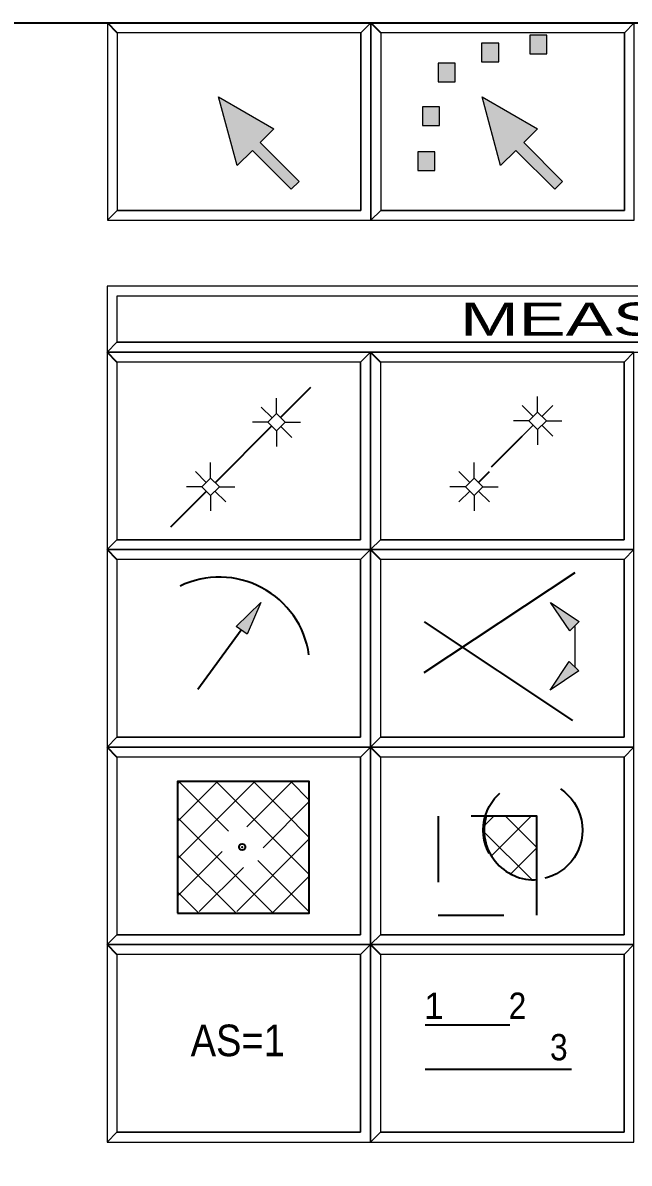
# Model space of a CAD drawing. Extents: x 95906.9 to 95918.9, y 90964.8 to 90972.9.
# Drawn here: x 95910.704 to 95911.625, y 90971.13 to 90972.862 of the extents above; entities that cross this region are included whole.
import ezdxf
from ezdxf.enums import TextEntityAlignment as Align

# ---------------------------------------------------------------- set-up
doc = ezdxf.new("R2010")
doc.units = 0
doc.header["$LTSCALE"] = 0.019
doc.header["$PDMODE"] = 32
doc.header["$PDSIZE"] = 0.0095
doc.linetypes.add('DOTTED', pattern=[1.5, 0.3, -1.2])
doc.linetypes.add('MEDIUM_DASHED', pattern=[4.5, 3, -1.5])
for name, color, linetype, lineweight in [('1', 7, 'Continuous', 25), ('11', 7, 'Continuous', 25), ('12', 7, 'Continuous', 25), ('2', 7, 'Continuous', 13), ('21', 7, 'Continuous', 25), ('3', 7, 'Continuous', 25), ('4', 7, 'Continuous', 35), ('6', 7, 'Continuous', 35), ('7', 7, 'Continuous', 35)]:
    doc.layers.add(name, color=color, linetype=linetype, lineweight=lineweight)

msp = doc.modelspace()

# ---------------------------------------------------------------- hatches: boundary and pattern name
at = {"layer": '6'}
for points in [[(95911.4737, 90972.8144), (95911.4997, 90972.8144), (95911.4997, 90972.8427), (95911.4737, 90972.8427)], [(95911.4005, 90972.8026), (95911.4265, 90972.8026), (95911.4265, 90972.8309), (95911.4005, 90972.8309)], [(95911.3344, 90972.7719), (95911.3604, 90972.7719), (95911.3604, 90972.8002), (95911.3344, 90972.8002)], [(95911.0012, 90972.7492), (95911.0851, 90972.7007), (95911.0644, 90972.68), (95911.1235, 90972.6209), (95911.1115, 90972.6089), (95911.0524, 90972.668), (95911.0292, 90972.6448)], [(95911.4012, 90972.7492), (95911.4851, 90972.7007), (95911.4644, 90972.68), (95911.5235, 90972.6209), (95911.5115, 90972.6089), (95911.4524, 90972.668), (95911.4292, 90972.6448)], [(95911.3107, 90972.7058), (95911.3367, 90972.7058), (95911.3367, 90972.7341), (95911.3107, 90972.7341)], [(95911.3036, 90972.6373), (95911.3296, 90972.6373), (95911.3296, 90972.6656), (95911.3036, 90972.6656)], [(95911.0277, 90971.945), (95911.0655, 90971.981), (95911.0443, 90971.9333)], [(95911.5346, 90971.938), (95911.505, 90971.981), (95911.5488, 90971.9526)], [(95911.5479, 90971.8772), (95911.5045, 90971.8482), (95911.5335, 90971.8916)]]:
    msp.add_hatch(color=256, dxfattribs=at).paths.add_polyline_path(points)

# ---------------------------------------------------------------- linework, layer by layer
at = {"layer": '1'}
for points in [[(95910.8323, 90972.5617), (95911.2323, 90972.5617), (95911.2323, 90972.8617), (95910.8323, 90972.8617)], [(95911.2323, 90972.5617), (95911.6323, 90972.5617), (95911.6323, 90972.8617), (95911.2323, 90972.8617)], [(95910.8318, 90972.3615), (95912.4318, 90972.3615), (95912.4318, 90972.4615), (95910.8318, 90972.4615)], [(95910.8318, 90972.0615), (95911.2318, 90972.0615), (95911.2318, 90972.3615), (95910.8318, 90972.3615)], [(95911.2318, 90972.0615), (95911.6318, 90972.0615), (95911.6318, 90972.3615), (95911.2318, 90972.3615)], [(95910.8318, 90971.7615), (95911.2318, 90971.7615), (95911.2318, 90972.0615), (95910.8318, 90972.0615)], [(95911.2318, 90971.7615), (95911.6318, 90971.7615), (95911.6318, 90972.0615), (95911.2318, 90972.0615)], [(95910.8318, 90971.4615), (95911.2318, 90971.4615), (95911.2318, 90971.7615), (95910.8318, 90971.7615)], [(95911.2318, 90971.4615), (95911.6318, 90971.4615), (95911.6318, 90971.7615), (95911.2318, 90971.7615)], [(95910.8318, 90971.1615), (95911.2318, 90971.1615), (95911.2318, 90971.4615), (95910.8318, 90971.4615)], [(95911.2318, 90971.1615), (95911.6318, 90971.1615), (95911.6318, 90971.4615), (95911.2318, 90971.4615)]]:
    msp.add_lwpolyline(points, close=True, dxfattribs=at)
at = {"layer": '11'}
for points in [[(95910.8473, 90972.5767), (95911.2173, 90972.5767), (95911.2173, 90972.8467), (95910.8473, 90972.8467)], [(95911.2473, 90972.5767), (95911.6173, 90972.5767), (95911.6173, 90972.8467), (95911.2473, 90972.8467)], [(95910.8468, 90972.0765), (95911.2168, 90972.0765), (95911.2168, 90972.3465), (95910.8468, 90972.3465)], [(95911.2468, 90972.0765), (95911.6168, 90972.0765), (95911.6168, 90972.3465), (95911.2468, 90972.3465)], [(95910.8468, 90971.7765), (95911.2168, 90971.7765), (95911.2168, 90972.0465), (95910.8468, 90972.0465)], [(95911.2468, 90971.7765), (95911.6168, 90971.7765), (95911.6168, 90972.0465), (95911.2468, 90972.0465)], [(95910.8468, 90971.4765), (95911.2168, 90971.4765), (95911.2168, 90971.7465), (95910.8468, 90971.7465)], [(95911.2468, 90971.4765), (95911.6168, 90971.4765), (95911.6168, 90971.7465), (95911.2468, 90971.7465)], [(95910.8468, 90971.1765), (95911.2168, 90971.1765), (95911.2168, 90971.4465), (95910.8468, 90971.4465)], [(95911.2468, 90971.1765), (95911.6168, 90971.1765), (95911.6168, 90971.4465), (95911.2468, 90971.4465)]]:
    msp.add_lwpolyline(points, close=True, dxfattribs=at)
at = {"layer": '12'}
msp.add_lwpolyline([(95910.8468, 90972.0765), (95911.2168, 90972.0765), (95911.2168, 90972.3465), (95910.8468, 90972.3465)], close=True, dxfattribs=at)
at = {"layer": '2'}
for points in [[(95910.8323, 90972.8617), (95910.8323, 90972.5617), (95910.8473, 90972.5767), (95910.8473, 90972.8467), (95911.2173, 90972.8467), (95911.2323, 90972.8617)], [(95911.2323, 90972.8617), (95911.2323, 90972.5617), (95911.2473, 90972.5767), (95911.2473, 90972.8467), (95911.6173, 90972.8467), (95911.6323, 90972.8617)], [(95910.8318, 90972.4615), (95910.8318, 90972.3615), (95910.8468, 90972.3765), (95910.8468, 90972.4465), (95912.4168, 90972.4465), (95912.4318, 90972.4615)], [(95910.8318, 90972.3615), (95910.8318, 90972.0615), (95910.8468, 90972.0765), (95910.8468, 90972.3465), (95911.2168, 90972.3465), (95911.2318, 90972.3615)], [(95911.2318, 90972.3615), (95911.2318, 90972.0615), (95911.2468, 90972.0765), (95911.2468, 90972.3465), (95911.6168, 90972.3465), (95911.6318, 90972.3615)], [(95910.8318, 90972.0615), (95910.8318, 90971.7615), (95910.8468, 90971.7765), (95910.8468, 90972.0465), (95911.2168, 90972.0465), (95911.2318, 90972.0615)], [(95911.2318, 90972.0615), (95911.2318, 90971.7615), (95911.2468, 90971.7765), (95911.2468, 90972.0465), (95911.6168, 90972.0465), (95911.6318, 90972.0615)], [(95910.8318, 90971.7615), (95910.8318, 90971.4615), (95910.8468, 90971.4765), (95910.8468, 90971.7465), (95911.2168, 90971.7465), (95911.2318, 90971.7615)], [(95911.2318, 90971.7615), (95911.2318, 90971.4615), (95911.2468, 90971.4765), (95911.2468, 90971.7465), (95911.6168, 90971.7465), (95911.6318, 90971.7615)], [(95910.8318, 90971.4615), (95910.8318, 90971.1615), (95910.8468, 90971.1765), (95910.8468, 90971.4465), (95911.2168, 90971.4465), (95911.2318, 90971.4615)], [(95911.2318, 90971.4615), (95911.2318, 90971.1615), (95911.2468, 90971.1765), (95911.2468, 90971.4465), (95911.6168, 90971.4465), (95911.6318, 90971.4615)]]:
    msp.add_lwpolyline(points, close=True, dxfattribs=at)
at = {"layer": '21'}
msp.add_lwpolyline([(95910.8468, 90972.3765), (95912.4168, 90972.3765), (95912.4168, 90972.4465), (95910.8468, 90972.4465)], close=True, dxfattribs=at)
at = {"layer": '3', "lineweight": 13}
msp.add_line((95910.8324, 90971.7587), (95910.8324, 90971.1626), dxfattribs=at)
at = {"layer": '3'}
for points in [[(95910.8323, 90972.5617), (95911.2323, 90972.5617), (95911.2323, 90972.8617), (95911.2173, 90972.8467), (95911.2173, 90972.5767), (95910.8473, 90972.5767)], [(95911.2323, 90972.5617), (95911.6323, 90972.5617), (95911.6323, 90972.8617), (95911.6173, 90972.8467), (95911.6173, 90972.5767), (95911.2473, 90972.5767)], [(95910.8318, 90972.3615), (95912.4318, 90972.3615), (95912.4318, 90972.4615), (95912.4168, 90972.4465), (95912.4168, 90972.3765), (95910.8468, 90972.3765)], [(95910.8318, 90972.0615), (95911.2318, 90972.0615), (95911.2318, 90972.3615), (95911.2168, 90972.3465), (95911.2168, 90972.0765), (95910.8468, 90972.0765)], [(95911.2318, 90972.0615), (95911.6318, 90972.0615), (95911.6318, 90972.3615), (95911.6168, 90972.3465), (95911.6168, 90972.0765), (95911.2468, 90972.0765)], [(95910.8318, 90971.7615), (95911.2318, 90971.7615), (95911.2318, 90972.0615), (95911.2168, 90972.0465), (95911.2168, 90971.7765), (95910.8468, 90971.7765)], [(95911.2318, 90971.7615), (95911.6318, 90971.7615), (95911.6318, 90972.0615), (95911.6168, 90972.0465), (95911.6168, 90971.7765), (95911.2468, 90971.7765)], [(95910.8318, 90971.4615), (95911.2318, 90971.4615), (95911.2318, 90971.7615), (95911.2168, 90971.7465), (95911.2168, 90971.4765), (95910.8468, 90971.4765)], [(95911.2318, 90971.4615), (95911.6318, 90971.4615), (95911.6318, 90971.7615), (95911.6168, 90971.7465), (95911.6168, 90971.4765), (95911.2468, 90971.4765)], [(95910.8318, 90971.1615), (95911.2318, 90971.1615), (95911.2318, 90971.4615), (95911.2168, 90971.4465), (95911.2168, 90971.1765), (95910.8468, 90971.1765)], [(95911.2318, 90971.1615), (95911.6318, 90971.1615), (95911.6318, 90971.4615), (95911.6168, 90971.4465), (95911.6168, 90971.1765), (95911.2468, 90971.1765)]]:
    msp.add_lwpolyline(points, close=True, dxfattribs=at)
at = {"layer": '4'}
for p, q in [((95910.8473, 90972.8467), (95910.8323, 90972.8617)), ((95911.2473, 90972.8467), (95911.2323, 90972.8617)), ((95910.8468, 90972.3465), (95910.8318, 90972.3615)), ((95910.8468, 90972.3465), (95910.8318, 90972.3615)), ((95911.2468, 90972.3465), (95911.2318, 90972.3615)), ((95910.8468, 90972.0465), (95910.8318, 90972.0615)), ((95911.2468, 90972.0465), (95911.2318, 90972.0615)), ((95910.8468, 90971.7465), (95910.8318, 90971.7615)), ((95911.2468, 90971.7465), (95911.2318, 90971.7615)), ((95910.8468, 90971.4465), (95910.8318, 90971.4615)), ((95911.2468, 90971.4465), (95911.2318, 90971.4615))]:
    msp.add_line(p, q, dxfattribs=at)
at = {"layer": '6'}
for p, q in [((95911.1405, 90972.308), (95911.0949, 90972.2624)), ((95911.0818, 90972.2493), (95910.9963, 90972.1637)), ((95910.9818, 90972.1493), (95910.928, 90972.0955)), ((95911.3134, 90971.8747), (95911.5425, 90972.0268)), ((95911.3134, 90971.9518), (95911.5384, 90971.8018)), ((95910.9697, 90971.8497), (95911.0354, 90971.9398)), ((95911.3148, 90971.3396), (95911.4434, 90971.3396)), ((95911.3148, 90971.2724), (95911.5368, 90971.2724))]:
    msp.add_line(p, q, dxfattribs=at)
at = {"layer": '6', "lineweight": 25}
for p, q in [((95911.0891, 90972.2682), (95911.0891, 90972.2916)), ((95911.4855, 90972.2705), (95911.4855, 90972.2939)), ((95911.0759, 90972.2549), (95911.0524, 90972.2549)), ((95911.1023, 90972.2549), (95911.1257, 90972.2549)), ((95911.4723, 90972.2572), (95911.4488, 90972.2572)), ((95911.4987, 90972.2572), (95911.5221, 90972.2572)), ((95911.0891, 90972.2417), (95911.0891, 90972.2183)), ((95911.4855, 90972.244), (95911.4855, 90972.2206)), ((95910.9891, 90972.1703), (95910.9891, 90972.1937)), ((95911.3891, 90972.1703), (95911.3891, 90972.1937)), ((95910.9759, 90972.157), (95910.9524, 90972.157)), ((95910.9891, 90972.1438), (95910.9891, 90972.1204)), ((95911.0023, 90972.157), (95911.0257, 90972.157)), ((95911.3759, 90972.157), (95911.3524, 90972.157)), ((95911.3891, 90972.1438), (95911.3891, 90972.1204)), ((95911.4023, 90972.157), (95911.4257, 90972.157)), ((95911.5421, 90971.9448), (95911.5421, 90971.8827))]:
    msp.add_line(p, q, dxfattribs=at)
at = {"layer": '6', "linetype": 'MEDIUM_DASHED', "lineweight": 13}
for p, q in [((95911.4789, 90972.2638), (95911.4623, 90972.2804)), ((95911.0825, 90972.2615), (95911.0659, 90972.2781)), ((95911.0957, 90972.2483), (95911.1123, 90972.2318)), ((95911.4921, 90972.2506), (95911.5087, 90972.2341)), ((95910.9825, 90972.1636), (95910.9659, 90972.1802)), ((95910.9957, 90972.1504), (95911.0123, 90972.1339)), ((95911.3957, 90972.1504), (95911.4123, 90972.1339))]:
    msp.add_line(p, q, dxfattribs=at)
at = {"layer": '6', "linetype": 'MEDIUM_DASHED', "lineweight": 25}
for p, q in [((95911.4921, 90972.2638), (95911.5087, 90972.2804)), ((95911.4789, 90972.2506), (95911.4623, 90972.2341)), ((95911.3825, 90972.1636), (95911.3659, 90972.1802)), ((95911.3825, 90972.1504), (95911.3659, 90972.1339))]:
    msp.add_line(p, q, dxfattribs=at)
at = {"layer": '6', "linetype": 'DOTTED'}
msp.add_line((95911.4154, 90972.1872), (95911.4623, 90972.2341), dxfattribs=at)
at = {"layer": '6', "linetype": 'MEDIUM_DASHED'}
msp.add_line((95911.3957, 90972.1636), (95911.4123, 90972.1802), dxfattribs=at)
at = {"layer": '6', "lineweight": 13}
for p, q in [((95910.9389, 90971.5919), (95911.0562, 90971.7092)), ((95910.9389, 90971.6485), (95910.9996, 90971.7092)), ((95910.9389, 90971.7051), (95910.943, 90971.7092)), ((95910.9409, 90971.7092), (95911.0163, 90971.6339)), ((95910.9975, 90971.7092), (95911.139, 90971.5677)), ((95911.044, 90971.6405), (95911.1127, 90971.7092)), ((95911.0541, 90971.7092), (95911.1007, 90971.6626)), ((95911.1106, 90971.7092), (95911.1389, 90971.6809)), ((95911.0687, 90971.6087), (95911.1389, 90971.6788)), ((95911.1012, 90971.6621), (95911.1389, 90971.6244)), ((95911.4029, 90971.6403), (95911.4192, 90971.6565)), ((95911.4157, 90971.5964), (95911.4758, 90971.6566)), ((95911.4378, 90971.6556), (95911.4847, 90971.6087)), ((95910.9389, 90971.6547), (95911.0832, 90971.5104)), ((95911.0286, 90971.5119), (95911.1389, 90971.6222)), ((95911.4046, 90971.6323), (95911.4762, 90971.5608)), ((95911.4439, 90971.5681), (95911.4845, 90971.6087)), ((95910.9389, 90971.5354), (95911.0065, 90971.603)), ((95910.9389, 90971.5981), (95911.0287, 90971.5083)), ((95911.0606, 90971.5895), (95911.1384, 90971.5117)), ((95910.9719, 90971.5118), (95911.0388, 90971.5787)), ((95911.0824, 90971.5092), (95911.1389, 90971.5657)), ((95910.9389, 90971.5415), (95910.9712, 90971.5092))]:
    msp.add_line(p, q, dxfattribs=at)
at = {"layer": '6', "lineweight": 25}
for points in [[(95911.4737, 90972.8144), (95911.4997, 90972.8144), (95911.4997, 90972.8427), (95911.4737, 90972.8427)], [(95911.4005, 90972.8026), (95911.4265, 90972.8026), (95911.4265, 90972.8309), (95911.4005, 90972.8309)], [(95911.3344, 90972.7719), (95911.3604, 90972.7719), (95911.3604, 90972.8002), (95911.3344, 90972.8002)], [(95911.0012, 90972.7492), (95911.0851, 90972.7007), (95911.0644, 90972.68), (95911.1235, 90972.6209), (95911.1115, 90972.6089), (95911.0524, 90972.668), (95911.0292, 90972.6448)], [(95911.4012, 90972.7492), (95911.4851, 90972.7007), (95911.4644, 90972.68), (95911.5235, 90972.6209), (95911.5115, 90972.6089), (95911.4524, 90972.668), (95911.4292, 90972.6448)], [(95911.3107, 90972.7058), (95911.3367, 90972.7058), (95911.3367, 90972.7341), (95911.3107, 90972.7341)], [(95911.3036, 90972.6373), (95911.3296, 90972.6373), (95911.3296, 90972.6656), (95911.3036, 90972.6656)], [(95911.4855, 90972.244), (95911.4988, 90972.2573), (95911.4855, 90972.2705), (95911.4722, 90972.2573)], [(95911.3891, 90972.1438), (95911.4024, 90972.1571), (95911.3891, 90972.1703), (95911.3758, 90972.1571)], [(95911.0277, 90971.945), (95911.0655, 90971.981), (95911.0443, 90971.9333)], [(95911.5346, 90971.938), (95911.505, 90971.981), (95911.5488, 90971.9526)], [(95911.5479, 90971.8772), (95911.5045, 90971.8482), (95911.5335, 90971.8916)]]:
    msp.add_lwpolyline(points, close=True, dxfattribs=at)
at = {"layer": '6', "lineweight": 13}
for points in [[(95911.0891, 90972.2417), (95911.1024, 90972.255), (95911.0891, 90972.2682), (95911.0758, 90972.255)], [(95910.9891, 90972.1438), (95911.0024, 90972.1571), (95910.9891, 90972.1703), (95910.9758, 90972.1571)]]:
    msp.add_lwpolyline(points, close=True, dxfattribs=at)
at = {"layer": '6'}
msp.add_lwpolyline([(95910.9389, 90971.5092), (95911.1389, 90971.5092), (95911.1389, 90971.7092), (95910.9389, 90971.7092)], close=True, dxfattribs=at)
at = {"layer": '6', "linetype": 'DOTTED'}
msp.add_lwpolyline([(95911.3344, 90971.5065), (95911.4844, 90971.5065), (95911.4844, 90971.6565), (95911.3344, 90971.6565)], close=True, dxfattribs=at)
at = {"layer": '6'}
msp.add_lwpolyline([(95911.4844, 90971.5558), (95911.4844, 90971.6565), (95911.4092, 90971.6565)], dxfattribs=at)
at = {"layer": '6', "linetype": 'DOTTED'}
msp.add_circle((95911.4783, 90971.6355), 0.0754, dxfattribs=at)
at = {"layer": '6'}
for centre, radius, start, end in [((95911.0024, 90971.8823), 0.1374, 8.167, 115.7914), ((95911.4798, 90971.6355), 0.0754, 163.6588, 274.1636)]:
    msp.add_arc(centre, radius, start, end, dxfattribs=at)
msp.add_point((95911.0369, 90971.6097), dxfattribs=at)
at = {"layer": '7'}
msp.add_lwpolyline([(95906.8548, 90972.8617), (95918.8548, 90972.8617), (95918.8548, 90964.7617), (95906.8548, 90964.7617)], close=True, dxfattribs=at)

# ---------------------------------------------------------------- texts
at = {"layer": '6'}
msp.add_text('1', height=0.04, dxfattribs=at).set_placement((95911.3281, 90971.3487), align=Align.CENTER)
at = {"layer": '6', "width": 0.9}
for s, height, p in [('2', 0.04, (95911.4549, 90971.3487)), ('AS=1', 0.048, (95911.0302, 90971.2921)), ('3', 0.04, (95911.5177, 90971.2858))]:
    msp.add_text(s, height=height, dxfattribs=at).set_placement(p, align=Align.CENTER)
at = {"layer": '7', "width": 1.6}
msp.add_text('        MEASURE        ', height=0.04999, dxfattribs=at).set_placement((95911.6322, 90972.3867), align=Align.CENTER)

doc.saveas('drawing.dxf')
